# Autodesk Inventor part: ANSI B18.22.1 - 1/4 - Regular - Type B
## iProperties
Comments: To add or edit properties for Autodesk Inventor files, use iProperties.
Created: 2005-06
Part Number: ANSI B18.22.1 - 1/4 - Regular - Type B
Vendor: Autodesk Inc.
Document SubType Name: Modeling
Designer: John Blackburn
Material: Default
Description: Washer B
Standard: ANSI B18.22.1
Size Designation: 1/4 - Regular - Type B
Alert: To add or edit properties for Autodesk Inventor files, use iProperties.
Control State: 0
Master: False
Checked Out: False
Shininess: 64.0
Length Units: 11272
Angle Units: 11279
Time Units: 11290
Mass Units: 11286
Length Display Precision: 3
Angle Display Precision: 2
Compacted: True
Classification: un/spsc 31161807
Density: 0.0
Volumn: 0.0
Area: 0.0
PropertySet Name: Model Information
Author: John Blackburn
Revision Number: 8
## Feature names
1. Body [Extrusion]
